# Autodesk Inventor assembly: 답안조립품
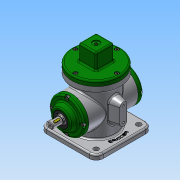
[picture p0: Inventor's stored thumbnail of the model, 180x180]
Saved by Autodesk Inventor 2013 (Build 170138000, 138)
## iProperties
Created: 2021-03
Part Number: 답안조립품
Document SubType Name: Assembly
Designer: Administrator
Author: Administrator
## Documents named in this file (15)
- C:\Users\Administrator\Desktop\710306V1005\답안조립품.iam
- C:\Users\Administrator\Desktop\710306V1005\본체.ipt
- C:\Users\Administrator\Desktop\710306V1005\베어링 17 x 40 x 12.ipt
- C:\Users\Administrator\Desktop\710306V1005\볼트 M4 x 10.ipt
- C:\Users\Administrator\Desktop\710306V1005\앞커버.ipt
- C:\Users\Administrator\Desktop\710306V1005\오일 실 17 30 8.ipt
- C:\Users\Administrator\Desktop\710306V1005\뒤커버.ipt
- C:\Users\Administrator\Desktop\710306V1005\덮개.ipt
- C:\Users\Administrator\Desktop\710306V1005\링크.ipt
- C:\Users\Administrator\Desktop\710306V1005\슬라이더.ipt
- C:\Users\Administrator\Desktop\710306V1005\클레비스 핀 6 x 22.ipt
- 클레비스 핀 6 x 22.ipt
- C:\Users\Administrator\Desktop\710306V1005\키 4 x 4 x 12.ipt
- C:\Users\Administrator\Desktop\710306V1005\편심축.ipt
- C:\Users\Administrator\Desktop\710306V1005\E-링.ipt
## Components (1 placed, 1 different names)
1. E-링:1
